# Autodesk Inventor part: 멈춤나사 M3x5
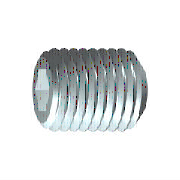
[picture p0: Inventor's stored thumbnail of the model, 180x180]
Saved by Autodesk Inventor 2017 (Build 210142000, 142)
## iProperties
Created: 2012-02
Part Number: 멈춤나사 M3x5
Material: 강철, 연강
Description: 6각 소켓 머리 없는 멈춤 나사
Document SubType Name: Modeling
Standard: KS B 1028
Designer: mduedu
Standards Organization: KS
Language: ko-KR
Size Designation: 납작점M3x5
Categories: <MemberInstance><Categories><Category DisplayName="조임쇠" InternalName="e4da775c-781d-43d5-af7c-5136215cf5a6" Mnemonic="FSTN"><Category DisplayName="볼트" InternalN
Density: 1 g/cm^3
Appearance: 노란색
IsCustomPart: 1
Author: mduedu
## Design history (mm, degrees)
sketch "스케치1"
  geometry: L1 (0, 0)-(2.5, 0); L2 (5, 0.866)-(5, 1.5); L3 (5, 1.5)-(0, 1.5); L4 (5, 0.866)-(3, 0.866); L5 (3, 0.866)-(2.5, 0); L6 (0, -0.3)-(0, 1.8) reference; L7 (0, 1.5)-(0, 0)
  constraints: 13 end point, 3 parallel, 1 collinear, 1 perpendicular, 1 point on line
  dimensions: "d0" = 2 distance of L2.start L4.end (= INTI); "d1" = 60 deg angle of L5 L1; "d2" = 3 diameter of L3 L1 (= NND); "d3" = 1.73205 diameter of L4 L1 (= 1.1547 x SW); "d5" = 5 distance from line of L2 L3.end (= NLG)
revolve "본체" sketch "스케치1" stored, may be unused: angle "d6" = 90 deg
sketch "스케치2"
  geometry: L1 (-0.433, 0.75)-(0.433, 0.75); L2 (0.433, 0.75)-(0.866, 0); L3 (0.866, 0)-(0.433, -0.75); L4 (0.433, -0.75)-(-0.433, -0.75); L5 (-0.433, -0.75)-(-0.866, 0); L6 (-0.866, 0)-(-0.433, 0.75); A1 r 0.866 centre (0, 0) between (-0.433, 0.75) and (0.433, 0.75) reference; 2 further points
  constraints: 12 end point, 2 point on circle, 1 coincident, 1 horizontal, 11 other
extrude "슬롯" join sketch "스케치2" taper "d9" = 0 deg; stored distance "d21" = 10
workaxis "Work Axis1"
workplane "Work Plane1"
body "Solid1"
chamfer "모따기1" distance "d7" = 0.30673 (= -0.5 x GD1 + 0.5 x NND); stored, may be unused: angle "d8" = 45 deg (= FAWI), second distance "d29" = 0.30673 (= -0.5 x GD1 + 0.5 x NND)
feature "스레드" dims "d11" = 5 (= NLG), "d12" = 0
chamfer "모따기2" distance "d13" = 0.30673 (= -0.5 x GD1 + 0.5 x NND); stored, may be unused: angle "d14" = 45 deg (= FAWI), second distance "d30" = 0.30673 (= -0.5 x GD1 + 0.5 x NND)
other parameters: "NND" = 3 [user parameter; used in 5 equation terms], "NLG" = 5 [user parameter; used in 2 equation terms], "INTI" = 2 [user parameter; used in 1 equation term], "FAWI" = 45 deg [user parameter; used in 2 equation terms], "SW" = 1.5 [user parameter; used in 2 equation terms], "GD1" = 2.38655 (= THREADDIA - 1.2269 x PTC) [user parameter; used in 4 equation terms], "d4" = 0, "FAWI1" = 45 deg [user parameter], "d15" = 0, "d31" = 0, "GUL" = 0.30673 (= 0.61345 x PTC) [user parameter], "SPD" = 2 [user parameter], "TOA" = 30 deg [user parameter], "THREADDIA" = 3 [user parameter; used in 1 equation term], "PTC" = 0.5 [user parameter; used in 4 equation terms], "GAL" = 0.30673 (= 0.61345 x PTC) [user parameter], "E0" = 1.7325 (= 1.155 x SW) [user parameter]
